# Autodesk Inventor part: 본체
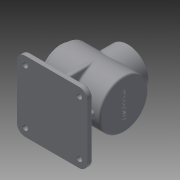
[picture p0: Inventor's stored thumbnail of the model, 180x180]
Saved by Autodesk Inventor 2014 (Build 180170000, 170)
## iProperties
Created: 2015-07
Part Number: 본체
Material: 일반
Document SubType Name: Modeling
Designer: Owner
Density: 1 g/cm^3
Appearance: 기본값
Author: Owner
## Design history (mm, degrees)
sketch "스케치1"
  geometry: L1 (-58.5, 0)-(58.5, 0); L2 (-58.5, 27)-(-58.5, 38); L3 (-58.5, 38)-(-51.5, 38); L4 (-51.5, 38)-(-51.5, 45); L5 (-51.5, 45)-(58.5, 45); L6 (58.5, 45)-(58.5, 0); L7 (-58.5, 27)-(-44.5, 27); L8 (-44.5, 27)-(-44.5, 40); L9 (-44.5, 40)-(51.5, 40); L10 (51.5, 40)-(51.5, 0); 2 further points
  constraints: 20 end point, 5 perpendicular, 4 parallel, 2 vertical alignment, 1 coincident, 1 horizontal, 1 midpoint, 1 point on line
  dimensions: "d0" = 90 diameter of L5 L1; "d1" = 117 distance of L1.start L1.end; "d2" = 54 diameter of L7 L1; "d3" = 80 diameter of L9 L1; "d4" = 7 distance of L2.end L3.end; "d5" = 14 distance of L2.start L7.end; "d6" = 96 distance of L8.end L9.end; "d7" = 76 diameter of L3 L1
revolve "회전1" sketch "스케치1" stored, may be unused: angle "d8" = 90 deg
node "작업 평면1"
sketch "스케치2"
  geometry: L1 (-58.5, 45)-(-58.5, -45) reference; C1 r 38 at (-3.5, 0); 1 further point
  constraints: 1 centre point, 1 horizontal alignment
  dimensions: "d10" = 76 diameter of C1; "d11" = 55 distance from line of C1.centre L1
extrude "돌출1" join sketch "스케치2" stored distance "d12" = 10; taper "d13" = 0 deg
node "작업 평면2"
sketch "스케치3"
  geometry: L1 (-68.5, 65)-(61.5, 65); L2 (61.5, 65)-(61.5, -65); L3 (61.5, -65)-(-68.5, -65); L4 (-68.5, -65)-(-68.5, 65); L5 (-58.5, 45)-(-58.5, -45) reference; 2 further points
  constraints: 8 end point, 2 parallel, 1 horizontal, 1 horizontal alignment, 1 midpoint, 1 perpendicular
  dimensions: "d15" = 130 distance of L2.end L3.end; "d16" = 130 distance of L1.end L2.end; "d17" = 10 distance between parallel lines of L4 L5
extrude "돌출2" join sketch "스케치3" distance "d18" = 10; taper "d19" = 0 deg
fillet "모깎기1" dims "d20" = 15
sketch "스케치5"
  geometry: C1 r 7.5 at (-46.5, -50); A1 r 15 centre (-46.5, -50) between (-61.5, -50) and (-46.5, -65) reference; 1 further point
  constraints: 1 centre point, 1 coincident
  dimensions: "d21" = 15 diameter of C1
extrude "돌출3" join sketch "스케치5" distance "d22" = 3; taper "d23" = 0 deg
hole "구멍1" diameter "d26" = 10; stored, may be unused: countersink angle "d30" = 90 deg, drill point angle "d32" = 118 deg; dims "d24" = 10, "d25" = 10, "d27" = 6, "d28" = 4, "d29" = 2, "d31" = 8
fillet "모깎기2" dims "d33" = 3
node "작업 평면3"
sketch "스케치6"
  geometry: L1 (0, 10)-(100, 10) reference; L2 (5, 10)-(5, 78); L3 (95, 10)-(95, 78); A1 r 45 centre (50, 78) between (5, 78) and (95, 78) reference; 1 further point
  constraints: 4 end point, 2 point on circle, 2 point on line, 1 parallel, 1 perpendicular
  dimensions: "d40" = 45 distance from line of point (50, 78) L2; "d41" = 90 distance between parallel lines of L2 L3
extrude "돌출4" join sketch "스케치6" stored distance "d42" = 10; taper "d43" = 0 deg
node "작업 평면4"
sketch "스케치7"
  geometry: L1 (0, 10)-(100, 10) reference; L2 (105, 33)-(-5, 33) reference; L3 (5, 10)-(5, 33); L4 (95, 10)-(95, 33); L5 (55, 78)-(45, 78) reference; L6 (100, 0)-(0, 0) reference; L7 (45, 78)-(45, 10) reference; L8 (55, 10)-(55, 78) reference; L9 (45, 10)-(55, 10) reference; L10 (100, 10)-(0, 10) reference; L11 (-15, 0)-(-15, 10) reference; 2 further points
  constraints: 4 end point, 4 point on line, 2 perpendicular, 1 midpoint
  dimensions: "d44" = 90 distance between parallel lines of L4 L3; "d45" = 65 distance from line of point (50, 10) L11; "d46" = 45 distance from line of point (50, 10) L3
hole "구멍2" diameter "d51" = 54; stored, may be unused: countersink angle "d55" = 90 deg, drill point angle "d57" = 118 deg; dims "d49" = 10, "d50" = 10, "d52" = 6, "d53" = 4, "d54" = 2, "d56" = 8
sketch "스케치8"
  geometry: C1 r 38 at (0, 0) reference; 1 further point
  constraints: 1 vertical alignment
  dimensions: "d58" = 32 distance of point (0, 32) C1.centre
hole "구멍3" sketch "스케치8" at (0, 32) diameter "d59" = 3.242; stored, may be unused: countersink angle "d63" = 90 deg, drill point angle "d65" = 118 deg; dims "d60" = 8, "d61" = 4, "d62" = 2, "d64" = 10
sketch "스케치9"
  geometry: C1 r 27 at (0, 0) reference; 2 further points
  constraints: 1 vertical alignment
  dimensions: "d69" = 32 distance of point (0, 32) C1.centre
hole "구멍4" sketch "스케치9" at (0, 32) diameter "d70" = 3.242; stored, may be unused: countersink angle "d74" = 90 deg, drill point angle "d76" = 118 deg; dims "d71" = 8, "d72" = 4, "d73" = 2, "d75" = 10
fillet "모깎기6" dims "d83" = 3
fillet "모깎기7" dims "d84" = 3
chamfer "모따기1" distance "d85" = 1; stored, may be unused: second distance "d86" = 2, angle "d87" = 45 deg
fillet "모깎기8" dims "d88" = 3
fillet "모깎기9" dims "d89" = 3
sketch "스케치10"
  geometry: C1 r 42 at (0, 0) reference; C2 r 45 at (0, 0) reference; 1 further point
  constraints: 1 coincident, 1 other
feature "엠보싱1" sketch "스케치10" dims "d0" = 90, "d1" = 117, "d2" = 54, "d3" = 80, "d4" = 7, "d5" = 14, "d6" = 96, "d7" = 76, "d90" = 0.5, "d91" = 0
fillet "모깎기10" dims "d92" = 3
node "작업 평면5"
sketch "스케치11"
  geometry: 1 further point
feature "리브1" dims "d94" = 1, "d95" = 10, "d96" = 0, "d97" = 0, "d98" = 1, "d99" = 1
sketch "스케치12"
  geometry: L1 (102, 33)-(-2, 33) reference; L2 (0, 10)-(100, 10) reference; L3 (95, 33)-(95, 10); L4 (5, 33.279)-(5, 10) reference; 1 further point
  constraints: 2 end point, 2 point on line, 1 perpendicular
  dimensions: "d100" = 90 distance between parallel lines of L3 L4
feature "리브2" sketch "스케치12" dims "d101" = 1, "d102" = 10, "d103" = 0, "d104" = 0, "d105" = 1, "d106" = 1
fillet "모깎기12" dims "d107" = 3
fillet "모깎기13" dims "d108" = 3
fillet "모깎기14" dims "d109" = 3
node "솔리드1"
pattern_linear "직사각형 패턴1"
pattern_circular "원형 패턴1" dims angle "d67" = 360 deg
pattern_circular "원형 패턴2" dims angle "d78" = 360 deg
other parameters: "d9" = 62, "d14" = -78
